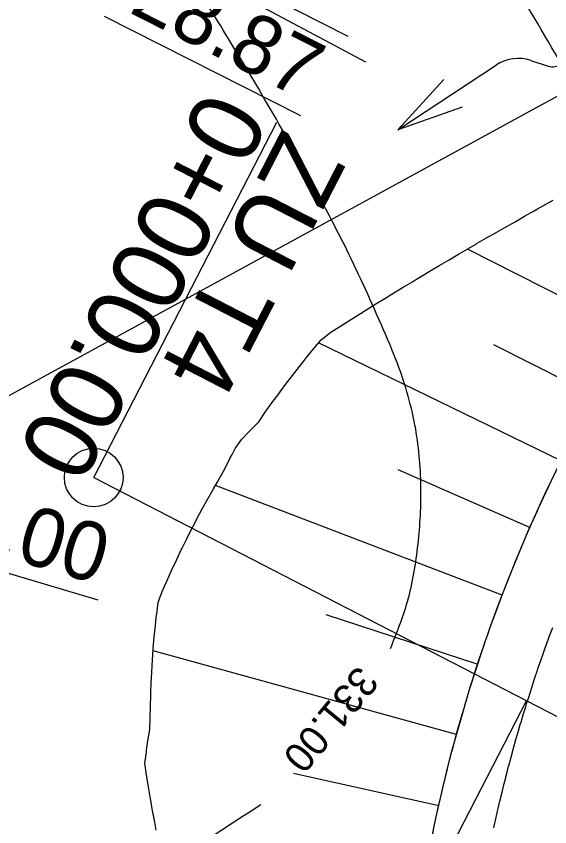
# Model space of a CAD drawing. Extents: x -564037 to -563827, y -1163561 to -1163412.
# Drawn here: x -563872.74 to -563863.65, y -1163500.35 to -1163486.54 of the extents above; entities that cross this region are included whole.
import ezdxf

# ---------------------------------------------------------------- set-up
doc = ezdxf.new("R2010")
doc.units = 0
for name, color, linetype in [('5', 7, 'Continuous'), ('_popis staničení PH4', 7, 'Continuous'), ('_popis staničení T4', 7, 'Continuous'), ('Line', 7, 'Continuous'), ('podélný profil', 7, 'Continuous'), ('Vrstva 24', 7, 'Continuous'), ('Vrstva 25', 7, 'Continuous'), ('Vrstva 26', 7, 'Continuous')]:
    doc.layers.add(name, color=color, linetype=linetype)

msp = doc.modelspace()

# ---------------------------------------------------------------- linework, layer by layer
for points in [[(-563866.782, -1163487.32), (-563875.054, -1163482.917), (-563879.887, -1163483.398)], [(-563870.356, -1163500.406), (-563870.382, -1163500.275), (-563870.42, -1163500.075), (-563870.457, -1163499.874), (-563870.491, -1163499.672), (-563870.524, -1163499.47), (-563870.549, -1163499.308), (-563870.552, -1163499.268), (-563870.526, -1163499.077), (-563870.522, -1163499.047), (-563870.499, -1163498.886), (-563870.469, -1163498.695), (-563870.461, -1163498.499), (-563870.458, -1163498.302), (-563870.452, -1163498.104), (-563870.45, -1163498.053), (-563870.444, -1163497.906), (-563870.434, -1163497.716), (-563870.434, -1163497.709), (-563870.421, -1163497.511), (-563870.407, -1163497.314), (-563870.39, -1163497.117), (-563870.371, -1163496.92), (-563870.357, -1163496.779), (-563870.35, -1163496.723), (-563870.327, -1163496.526), (-563870.273, -1163496.384), (-563870.256, -1163496.344), (-563870.177, -1163496.164), (-563870.097, -1163495.985), (-563870.014, -1163495.807), (-563869.93, -1163495.63), (-563869.915, -1163495.6), (-563869.843, -1163495.454), (-563869.755, -1163495.279), (-563869.702, -1163495.177), (-563869.664, -1163495.105), (-563869.572, -1163494.933), (-563869.477, -1163494.761), (-563869.381, -1163494.59), (-563869.32, -1163494.483), (-563869.283, -1163494.421), (-563869.19, -1163494.249), (-563869.102, -1163494.077), (-563869.066, -1163494.008), (-563869.011, -1163493.905), (-563868.898, -1163493.743), (-563868.754, -1163493.595), (-563868.609, -1163493.448), (-563868.599, -1163493.434), (-563868.498, -1163493.287), (-563868.385, -1163493.128), (-563868.27, -1163492.97), (-563868.246, -1163492.937), (-563868.154, -1163492.813), (-563868.036, -1163492.658), (-563867.916, -1163492.504), (-563867.85, -1163492.42), (-563867.795, -1163492.351), (-563867.672, -1163492.2), (-563867.547, -1163492.05), (-563867.383, -1163491.921), (-563867.379, -1163491.919), (-563867.23, -1163491.824), (-563867.077, -1163491.728), (-563866.923, -1163491.632), (-563866.769, -1163491.536), (-563866.615, -1163491.441), (-563866.46, -1163491.346), (-563866.305, -1163491.251), (-563866.149, -1163491.156), (-563865.992, -1163491.062), (-563865.92, -1163491.018), (-563865.836, -1163490.967), (-563865.678, -1163490.873), (-563865.521, -1163490.78), (-563865.362, -1163490.686), (-563865.204, -1163490.593), (-563865.044, -1163490.5), (-563864.898, -1163490.415), (-563864.885, -1163490.407), (-563864.725, -1163490.315), (-563864.564, -1163490.222), (-563864.403, -1163490.13), (-563864.241, -1163490.039), (-563864.079, -1163489.947), (-563863.917, -1163489.856), (-563863.856, -1163489.822), (-563863.754, -1163489.765), (-563863.59, -1163489.674)], [(-563865.785, -1163501.206), (-563865.619, -1163500.343), (-563865.574, -1163500.129), (-563865.385, -1163499.33), (-563865.317, -1163499.063), (-563865.111, -1163498.327), (-563865.015, -1163498.009), (-563864.797, -1163497.335), (-563864.669, -1163496.968), (-563864.528, -1163496.58), (-563864.443, -1163496.357), (-563864.28, -1163495.943), (-563864.051, -1163495.394), (-563863.848, -1163494.935), (-563863.62, -1163494.448), (-563863.373, -1163493.946), (-563863.165, -1163493.533), (-563862.713, -1163492.641), (-563862.262, -1163491.749), (-563861.987, -1163491.206), (-563861.81, -1163490.857), (-563861.359, -1163489.964), (-563861.279, -1163489.807)], [(-563865.645, -1163500.469), (-563865.619, -1163500.343), (-563865.613, -1163500.311), (-563865.579, -1163500.154), (-563865.574, -1163500.129), (-563865.544, -1163499.997), (-563865.508, -1163499.84), (-563865.472, -1163499.683), (-563865.434, -1163499.526), (-563865.395, -1163499.37), (-563865.385, -1163499.33), (-563865.356, -1163499.214), (-563865.317, -1163499.063), (-563865.315, -1163499.058), (-563865.274, -1163498.902), (-563865.231, -1163498.747), (-563865.188, -1163498.592), (-563865.143, -1163498.437), (-563865.111, -1163498.327), (-563865.098, -1163498.283), (-563865.052, -1163498.128), (-563865.015, -1163498.009), (-563865.004, -1163497.974), (-563864.956, -1163497.821), (-563864.907, -1163497.667), (-563864.857, -1163497.514), (-563864.806, -1163497.362), (-563864.797, -1163497.335), (-563864.754, -1163497.209), (-563864.701, -1163497.057), (-563864.669, -1163496.968), (-563864.647, -1163496.905), (-563864.592, -1163496.754), (-563864.536, -1163496.603), (-563864.48, -1163496.452), (-563864.443, -1163496.357), (-563864.422, -1163496.302), (-563864.363, -1163496.152), (-563864.304, -1163496.002), (-563864.28, -1163495.943), (-563864.243, -1163495.853), (-563864.182, -1163495.704), (-563864.12, -1163495.555), (-563864.056, -1163495.407), (-563864.051, -1163495.394), (-563863.992, -1163495.259), (-563863.927, -1163495.112), (-563863.861, -1163494.965), (-563863.848, -1163494.935), (-563863.795, -1163494.819), (-563863.727, -1163494.673), (-563863.658, -1163494.527), (-563863.62, -1163494.448)], [(-563864.602, -1163500.367), (-563864.597, -1163500.343), (-563864.568, -1163500.215), (-563864.534, -1163500.064), (-563864.499, -1163499.914), (-563864.462, -1163499.763), (-563864.425, -1163499.613), (-563864.416, -1163499.574), (-563864.387, -1163499.463), (-563864.35, -1163499.318), (-563864.348, -1163499.313), (-563864.308, -1163499.163), (-563864.267, -1163499.014), (-563864.226, -1163498.865), (-563864.183, -1163498.716), (-563864.152, -1163498.61), (-563864.139, -1163498.567), (-563864.095, -1163498.419), (-563864.06, -1163498.304), (-563864.049, -1163498.271), (-563864.003, -1163498.123), (-563863.956, -1163497.976), (-563863.908, -1163497.829), (-563863.858, -1163497.682), (-563863.85, -1163497.656), (-563863.808, -1163497.535), (-563863.757, -1163497.389), (-563863.727, -1163497.303), (-563863.706, -1163497.243), (-563863.653, -1163497.097), (-563863.599, -1163496.952)]]:
    msp.add_lwpolyline(points)
at = {"layer": '5'}
for p, q in [((-563897.15, -1163506.247), (-563862.812, -1163487.513)), ((-563871.424, -1163494.398), (-563841.172, -1163509.993))]:
    msp.add_line(p, q, dxfattribs=at)
at = {"layer": '_popis staničení PH4'}
for p, q in [((-563867.083, -1163486.881), (-563870.429, -1163485.188)), ((-563867.894, -1163488.236), (-563871.24, -1163486.543)), ((-563867.893, -1163488.234), (-563871.239, -1163486.541)), ((-563871.345, -1163496.487), (-563874.942, -1163495.426))]:
    msp.add_line(p, q, dxfattribs=at)
at = {"layer": '_popis staničení T4'}
for points in [[(-563871.424, -1163494.398), (-563868.303, -1163488.344)], [(-563864.047, -1163498.201), (-563874.905, -1163519.264)]]:
    msp.add_lwpolyline(points, dxfattribs=at)
msp.add_circle((-563871.424, -1163494.398), 0.5, dxfattribs=at)
at = {"layer": 'Line'}
for p, q in [((-563862.33, -1163491.884), (-563865.054, -1163490.506)), ((-563863.457, -1163494.115), (-563867.593, -1163492.106)), ((-563864.611, -1163492.132), (-563862.894, -1163492.999)), ((-563866.237, -1163494.262), (-563863.986, -1163495.248)), ((-563864.459, -1163496.404), (-563869.35, -1163494.536)), ((-563867.464, -1163496.734), (-563864.877, -1163497.582)), ((-563865.238, -1163498.779), (-563870.41, -1163497.354)), ((-563868.019, -1163499.435), (-563865.541, -1163499.991))]:
    msp.add_line(p, q, dxfattribs=at)
at = {"layer": 'podélný profil'}
for points in [[(-563863.97, -1163487.29), (-563863.678, -1163487.388)], [(-563866.242, -1163488.471), (-563864.555, -1163487.366)], [(-563865.144, -1163488.089), (-563866.242, -1163488.471), (-563865.453, -1163487.617)]]:
    msp.add_lwpolyline(points, dxfattribs=at)
for centre, radius, start, end in [((-563863.607, -1163487.174), 0.226, 251.5312, 10.0782), ((-563864.184, -1163487.932), 0.677, 71.5291, 123.2236)]:
    msp.add_arc(centre, radius, start, end, dxfattribs=at)
at = {"layer": 'Vrstva 24'}
for points in [[(-563866.364, -1163497.311), (-563866.075, -1163496.511), (-563865.895, -1163495.533), (-563865.845, -1163494.553), (-563865.947, -1163493.507), (-563866.272, -1163492.388), (-563866.563, -1163491.699), (-563866.868, -1163491.02), (-563867.192, -1163490.352), (-563867.536, -1163489.691), (-563869.125, -1163486.92), (-563869.85, -1163485.772), (-563870.624, -1163484.653), (-563871.666, -1163483.346), (-563872.824, -1163482.142), (-563874.562, -1163480.618), (-563875.472, -1163479.893), (-563878.363, -1163477.556), (-563882.755, -1163474.046), (-563884.234, -1163472.969), (-563885.61, -1163472.026), (-563886.998, -1163471.1), (-563889.83, -1163469.34), (-563892.347, -1163467.891)], [(-563852.947, -1163500.287), (-563852.983, -1163499.934), (-563853.278, -1163497.907), (-563853.324, -1163497.501), (-563853.384, -1163496.604), (-563853.408, -1163496.155), (-563853.449, -1163495.707), (-563853.76, -1163494.797), (-563854.364, -1163493.737), (-563856.816, -1163489.636), (-563859.313, -1163485.439), (-563859.915, -1163484.694), (-563860.397, -1163484.207), (-563862.509, -1163482.09), (-563867.011, -1163477.664), (-563868.116, -1163476.702), (-563871.116, -1163474.41), (-563872.986, -1163473.06), (-563873.689, -1163472.566), (-563878.103, -1163469.411), (-563878.316, -1163469.26)], [(-563905.221, -1163519.388), (-563901.417, -1163517.444), (-563900.291, -1163516.907), (-563895.909, -1163514.815), (-563892.135, -1163512.984), (-563890.63, -1163512.267), (-563888.864, -1163511.357), (-563887.99, -1163510.869), (-563887.125, -1163510.367), (-563886.26, -1163509.866), (-563885.383, -1163509.384), (-563882.362, -1163507.826), (-563880.585, -1163506.938), (-563878.549, -1163505.818), (-563872.848, -1163502.599), (-563870.632, -1163501.288), (-563869.542, -1163500.601), (-563868.575, -1163499.969)]]:
    msp.add_spline(points, degree=3, dxfattribs=at)
at = {"layer": 'Vrstva 26'}
for points in [[(-563838.029, -1163497.163), (-563838.58, -1163496.19), (-563840.28, -1163493.165), (-563841.199, -1163491.578), (-563841.674, -1163490.793), (-563842.159, -1163490.013), (-563843.649, -1163487.993), (-563844.702, -1163486.757), (-563850.461, -1163480.038), (-563851.089, -1163479.371), (-563851.956, -1163478.574), (-563857.613, -1163473.501), (-563859.731, -1163471.636), (-563864.022, -1163468.083), (-563864.562, -1163467.631), (-563865.045, -1163467.216), (-563865.679, -1163466.68)], [(-563859.41, -1163497.306), (-563859.213, -1163496.32), (-563859.173, -1163495.343), (-563859.23, -1163495.062), (-563859.315, -1163494.786), (-563859.559, -1163494.264), (-563860.664, -1163492.33), (-563861.767, -1163490.395), (-563863.612, -1163487.077), (-563864.619, -1163485.435), (-563865.167, -1163484.642), (-563865.744, -1163483.864), (-563868.01, -1163481.46), (-563871.348, -1163478.665), (-563874.529, -1163476.131), (-563879.25, -1163472.365), (-563881.038, -1163471.025), (-563881.839, -1163470.479), (-563883.542, -1163469.415), (-563886.341, -1163467.718)], [(-563846.143, -1163505.119), (-563846.16, -1163504.298), (-563846.784, -1163499.435), (-563846.859, -1163499.141), (-563847.15, -1163498.47), (-563847.685, -1163497.291), (-563847.809, -1163497.032), (-563850.257, -1163492.396), (-563853.06, -1163487.093), (-563853.131, -1163486.997), (-563856.933, -1163483.04), (-563859.434, -1163480.56), (-563863.484, -1163476.533), (-563865.168, -1163474.917), (-563866.123, -1163474.143), (-563868.988, -1163472.112)]]:
    msp.add_spline(points, degree=3, dxfattribs=at)

# ---------------------------------------------------------------- texts
at = {"layer": '_popis staničení PH4'}
for s, rotation, p in [('28.87', 333.161, (-563870.842, -1163486.462)), ('20.00', 343.5615, (-563874.562, -1163495.277))]:
    msp.add_text(s, height=1, rotation=rotation, dxfattribs=at).set_placement(p)
at = {"layer": '_popis staničení T4'}
for s, p in [('0+000.00', (-563869.528, -1163487.74)), ('ZU T4 ', (-563868.194, -1163488.427))]:
    msp.add_text(s, height=1.25, rotation=242.7291, dxfattribs=at).set_placement(p)
at = {"layer": 'Vrstva 25'}
msp.add_text('331.00', height=0.5, rotation=230.2626, dxfattribs=at).set_placement((-563866.917, -1163497.579))

doc.saveas('drawing.dxf')
